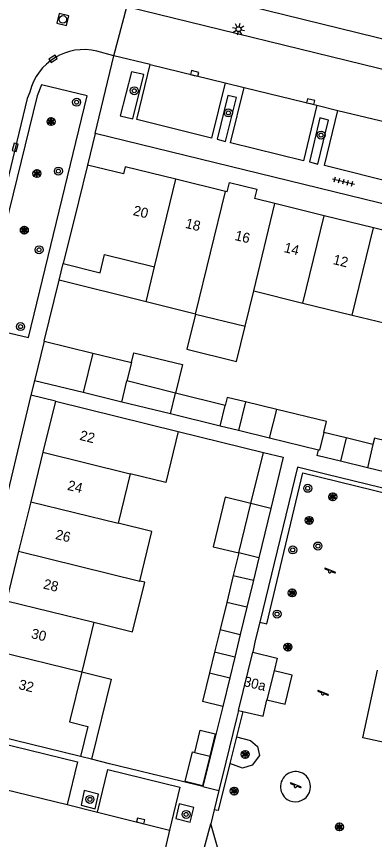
# Model space of a CAD drawing. Extents: x 128000 to 131008, y 398996 to 402500.
# Drawn here: x 128150.1 to 128186, y 399561.8 to 399644.1 of the extents above; entities that cross this region are included whole.
import ezdxf

# ---------------------------------------------------------------- set-up
doc = ezdxf.new("R2010")
doc.units = 0
for name, color, linetype in [('gg-afsc-hekwerk', 7, 'Continuous'), ('gg-afsc-muur', 7, 'Continuous'), ('gg-anno-huisnummerreeks BGT', 7, 'Continuous'), ('gg-bbg-bijgebouw', 7, 'Continuous'), ('gg-bbg-gedigitaliseerde bebouwing', 7, 'Continuous'), ('gg-bbg-gedigitaliseerde bijgebouw', 7, 'Continuous'), ('gg-bbg-hoofdgebouw', 7, 'Continuous'), ('gg-bbg-luifel en loopbrug', 7, 'Continuous'), ('gg-bbg-tussenscheiding', 7, 'Continuous'), ('gg-knt-verharding', 7, 'Continuous'), ('gg-knt-verharding nz', 7, 'Continuous'), ('gt-grn-groengrens', 7, 'Continuous'), ('gt-grn-weggrens', 7, 'Continuous'), ('gt-symb-boom', 7, 'Continuous'), ('gt-symb-kolk', 7, 'Continuous'), ('gt-symb-lichtmast', 7, 'Continuous'), ('gt-symb-rioolschacht', 7, 'Continuous'), ('gt-symb-solitaire heester', 7, 'Continuous'), ('gt-symb-speelvoorziening', 7, 'Continuous'), ('gt-symb-tegel verharding', 7, 'Continuous')]:
    doc.layers.add(name, color=color, linetype=linetype)

# ---------------------------------------------------------------- blocks, each defined once
blk = doc.blocks.new('gt0-BOOM')
at = {"layer": 'gt-symb-boom'}
for radius in [0.4, 0.2]:
    blk.add_circle((0, 0), radius, dxfattribs=at)
blk = doc.blocks.new('gt0-KOLK')
at = {"layer": 'gt-symb-kolk'}
blk.add_lwpolyline([(0, 0), (0.375, 0), (0.375, 0.4), (-0.375, 0.4), (-0.375, 0), (0, 0)], dxfattribs=at)
blk = doc.blocks.new('gt0-LMAST')
at = {"layer": 'gt-symb-lichtmast'}
for p, q in [((-0.182, 0.173), (-0.447, 0.438)), ((-0.005, 0.246), (-0.005, 0.621)), ((0.172, 0.173), (0.437, 0.438)), ((-0.255, -0.004), (-0.63, -0.004)), ((-0.182, -0.181), (-0.447, -0.446)), ((-0.005, -0.254), (-0.005, -0.629)), ((0.437, -0.446), (0.172, -0.181)), ((0.245, -0.004), (0.62, -0.004))]:
    blk.add_line(p, q, dxfattribs=at)
blk.add_circle((-0.005, -0.004), 0.25, dxfattribs=at)
blk = doc.blocks.new('gt0-TEG1')
at = {"layer": 'gt-symb-tegel verharding'}
for p, q in [((-1.125, 0), (1.125, 0)), ((-0.9, -0.25), (-0.9, 0.25)), ((-0.45, -0.25), (-0.45, 0.25)), ((0, -0.25), (0, 0.25)), ((0.45, -0.25), (0.45, 0.25)), ((0.9, -0.25), (0.9, 0.25))]:
    blk.add_line(p, q, dxfattribs=at)
blk = doc.blocks.new('gt0-SH')
at = {"layer": 'gt-symb-solitaire heester'}
blk.add_circle((0, 0), 0.4, dxfattribs=at)
for centre, start, end in [((-0.346, 0.2), 270, 30), ((-0.346, -0.2), 330, 90), ((0, 0.4), 210, 330), ((0.346, 0.2), 150, 270), ((0.346, -0.2), 90, 210), ((0, -0.4), 30, 150)]:
    blk.add_arc(centre, 0.4, start, end, dxfattribs=at)
blk = doc.blocks.new('gt0-RS')
at = {"layer": 'gt-symb-rioolschacht'}
blk.add_lwpolyline([(-0.5, -0.5), (0.5, -0.5), (0.5, 0.5), (-0.5, 0.5)], close=True, dxfattribs=at)
blk.add_circle((0, 0), 0.375, dxfattribs=at)
blk = doc.blocks.new('gt0-SV')
at = {"layer": 'gt-symb-speelvoorziening'}
for p, q in [((-0.477, 0.255), (-0.08, 0.096)), ((0.542, -0.076), (-0.449, 0.324)), ((0.125, 0.014), (0.515, -0.143))]:
    blk.add_line(p, q, dxfattribs=at)
for centre, radius, start, end in [((-0.466, 0.291), 0.0369, 63.6251, 252.66016), ((-0.002, -0.005), 0.128, 127.68665, 8.59861), ((0.531, -0.111), 0.0363, 243.50852, 72.54358)]:
    blk.add_arc(centre, radius, start, end, dxfattribs=at)

msp = doc.modelspace()

# ---------------------------------------------------------------- linework, layer by layer
at = {"layer": 'gg-afsc-hekwerk'}
for p, q in [((128203.553, 399592.827), (128181.209, 399598.288)), ((128171.084, 399569.505), (128170.393, 399566.665)), ((128170.393, 399566.665), (128169.92, 399564.721)), ((128169.92, 399564.721), (128169.58, 399563.327)), ((128170.982, 399558.462), (128169.58, 399563.327))]:
    msp.add_line(p, q, dxfattribs=at)
for points in [[(128181.209, 399598.288), (128178.265, 399599.008), (128174.493, 399583.51)], [(128174.493, 399583.51), (128174.043, 399581.663), (128173.796, 399580.492)], [(128172.372, 399574.674), (128172.145, 399573.865), (128171.084, 399569.505)]]:
    msp.add_lwpolyline(points, dxfattribs=at)
at = {"layer": 'gg-afsc-muur'}
for p, q in [((128152.897, 399611.62), (128154.389, 399617.73)), ((128166.312, 399602.605), (128174.854, 399600.506)), ((128170.783, 399575.069), (128168.797, 399567.055)), ((128159.426, 399569.345), (128157.621, 399569.786)), ((128166.623, 399567.586), (128159.426, 399569.345)), ((128168.797, 399567.055), (128166.623, 399567.586))]:
    msp.add_line(p, q, dxfattribs=at)
at = {"layer": 'gg-bbg-bijgebouw'}
for p, q in [((128152.897, 399611.62), (128151.932, 399607.671)), ((128156.798, 399606.485), (128151.932, 399607.671)), ((128165.548, 399604.353), (128160.667, 399605.542)), ((128170.52, 399603.141), (128165.548, 399604.353)), ((128175.477, 399601.933), (128172.373, 399602.689)), ((128180.377, 399600.739), (128175.477, 399601.933)), ((128185.268, 399598.962), (128182.569, 399599.625)), ((128190.194, 399597.752), (128185.268, 399598.962)), ((128175.605, 399594.896), (128174.401, 399589.946)), ((128173.854, 399587.697), (128173.197, 399584.995)), ((128173.197, 399584.995), (128172.539, 399582.291)), ((128171.485, 399577.954), (128170.783, 399575.069)), ((128170.783, 399575.069), (128168.76, 399575.57))]:
    msp.add_line(p, q, dxfattribs=at)
msp.add_lwpolyline([(128174.854, 399600.506), (128176.849, 399600.012), (128175.605, 399594.896)], dxfattribs=at)
at = {"layer": 'gg-bbg-gedigitaliseerde bebouwing'}
for p, q in [((128163.094, 399615.561), (128163.958, 399619.088)), ((128173.03, 399613.127), (128173.894, 399616.656)), ((128173.894, 399616.656), (128178.819, 399615.451)), ((128168.065, 399614.343), (128163.094, 399615.561)), ((128178.819, 399615.451), (128183.762, 399614.241)), ((128168.065, 399614.343), (128173.03, 399613.127)), ((128183.762, 399614.241), (128188.706, 399613.032)), ((128161.501, 399598.358), (128160.291, 399593.406)), ((128157.87, 399583.495), (128156.658, 399578.537))]:
    msp.add_line(p, q, dxfattribs=at)
for points in [[(128158.5, 399618.47), (128158.948, 399620.314), (128163.958, 399619.088)], [(128166.312, 399602.605), (128165.069, 399597.485), (128161.501, 399598.358)], [(128162.476, 399587.62), (128163.69, 399592.572), (128160.291, 399593.406)], [(128157.87, 399583.495), (128161.745, 399582.544), (128162.961, 399587.501), (128162.476, 399587.62)], [(128156.658, 399578.537), (128155.432, 399573.522), (128157.28, 399573.07)]]:
    msp.add_lwpolyline(points, dxfattribs=at)
at = {"layer": 'gg-bbg-gedigitaliseerde bijgebouw'}
for p, q in [((128152.897, 399611.62), (128157.76, 399610.432)), ((128157.76, 399610.432), (128156.798, 399606.485)), ((128160.667, 399605.542), (128161.178, 399607.65)), ((128166.05, 399606.413), (128161.178, 399607.65)), ((128171.021, 399605.201), (128166.05, 399606.413)), ((128170.52, 399603.141), (128171.021, 399605.201)), ((128173.07, 399605.548), (128172.373, 399602.689)), ((128176.184, 399604.789), (128173.07, 399605.548)), ((128183.134, 399601.944), (128182.569, 399599.625)), ((128185.834, 399601.287), (128183.134, 399601.944)), ((128173.596, 399595.381), (128174.854, 399600.506)), ((128172.384, 399590.436), (128173.596, 399595.381)), ((128174.401, 399589.946), (128172.384, 399590.436)), ((128171.836, 399588.188), (128171.178, 399585.487)), ((128171.836, 399588.188), (128173.854, 399587.697)), ((128171.178, 399585.487), (128170.519, 399582.783)), ((128170.519, 399582.783), (128172.539, 399582.291)), ((128169.462, 399578.448), (128168.76, 399575.57)), ((128169.462, 399578.448), (128171.485, 399577.954)), ((128167.98, 399570.459), (128169.491, 399570.09))]:
    msp.add_line(p, q, dxfattribs=at)
for points in [[(128180.899, 399602.488), (128181.165, 399603.577), (128176.184, 399604.789)], [(128180.899, 399602.488), (128180.468, 399600.717), (128180.377, 399600.739)], [(128190.924, 399600.71), (128185.986, 399601.912), (128185.834, 399601.287)], [(128167.02, 399567.562), (128167.742, 399570.518), (128167.98, 399570.459)], [(128169.491, 399570.09), (128168.769, 399567.135), (128167.02, 399567.562)]]:
    msp.add_lwpolyline(points, dxfattribs=at)
at = {"layer": 'gg-bbg-hoofdgebouw'}
for p, q in [((128157.233, 399629.251), (128156.339, 399625.59)), ((128166.084, 399627.835), (128161, 399629.08)), ((128171.046, 399626.62), (128166.084, 399627.835)), ((128171.22, 399626.577), (128171.046, 399626.62)), ((128176.007, 399625.405), (128173.96, 399625.906)), ((128156.339, 399625.59), (128154.797, 399619.402)), ((128180.959, 399624.192), (128176.007, 399625.405)), ((128185.892, 399622.984), (128180.959, 399624.192)), ((128190.863, 399621.767), (128185.892, 399622.984)), ((128154.797, 399619.402), (128158.5, 399618.47)), ((128154.011, 399605.626), (128152.756, 399600.51)), ((128154.011, 399605.626), (128166.312, 399602.605)), ((128152.756, 399600.51), (128151.541, 399595.557)), ((128151.541, 399595.557), (128150.326, 399590.604)), ((128150.326, 399590.604), (128149.111, 399585.651)), ((128172.372, 399574.674), (128173.796, 399580.492)), ((128173.796, 399580.492), (128176.225, 399579.898)), ((128176.225, 399579.898), (128175.917, 399578.635)), ((128175.917, 399578.635), (128175.213, 399575.742)), ((128172.372, 399574.674), (128172.785, 399574.579)), ((128157.28, 399573.07), (128156.54, 399570.05)), ((128156.54, 399570.05), (128147.86, 399572.18))]:
    msp.add_line(p, q, dxfattribs=at)
for points in [[(128161, 399629.08), (128160.826, 399628.371), (128157.233, 399629.251)], [(128171.22, 399626.577), (128171.451, 399627.52), (128174.193, 399626.858), (128173.96, 399625.906)], [(128172.785, 399574.579), (128174.816, 399574.11), (128175.213, 399575.742)]]:
    msp.add_lwpolyline(points, dxfattribs=at)
at = {"layer": 'gg-bbg-luifel en loopbrug'}
for p, q in [((128154.389, 399617.73), (128154.797, 399619.402)), ((128163.094, 399615.561), (128154.389, 399617.73)), ((128157.76, 399610.432), (128161.625, 399609.488)), ((128161.625, 399609.488), (128161.178, 399607.65)), ((128160.667, 399605.542), (128156.798, 399606.485)), ((128172.373, 399602.689), (128170.52, 399603.141)), ((128183.134, 399601.944), (128180.899, 399602.488)), ((128182.569, 399599.625), (128180.335, 399600.173)), ((128172.384, 399590.436), (128171.836, 399588.188)), ((128174.401, 399589.946), (128173.854, 399587.697)), ((128170.519, 399582.783), (128169.964, 399580.508)), ((128172.539, 399582.291), (128171.986, 399580.016)), ((128169.964, 399580.508), (128169.462, 399578.448)), ((128171.986, 399580.016), (128169.964, 399580.508)), ((128171.986, 399580.016), (128171.485, 399577.954)), ((128157.621, 399569.786), (128156.54, 399570.05))]:
    msp.add_line(p, q, dxfattribs=at)
for points in [[(128168.065, 399614.343), (128167.19, 399610.833), (128172.15, 399609.597), (128173.03, 399613.127)], [(128161.625, 399609.488), (128161.867, 399610.479), (128166.751, 399609.289), (128166.05, 399606.413)], [(128173.07, 399605.548), (128171.216, 399605.999), (128171.021, 399605.201)], [(128180.335, 399600.173), (128180.243, 399600.196), (128180.377, 399600.739)], [(128173.596, 399595.381), (128171.036, 399596.004), (128169.831, 399591.058), (128172.384, 399590.436)], [(128156.658, 399578.537), (128159.592, 399577.817), (128157.621, 399569.786)], [(128167.98, 399570.459), (128168.523, 399572.686), (128170.035, 399572.317), (128169.491, 399570.09)]]:
    msp.add_lwpolyline(points, dxfattribs=at)
at = {"layer": 'gg-bbg-tussenscheiding'}
for p, q in [((128163.958, 399619.088), (128166.084, 399627.835)), ((128168.065, 399614.343), (128171.046, 399626.62)), ((128173.894, 399616.656), (128176.007, 399625.405)), ((128178.819, 399615.451), (128180.959, 399624.192)), ((128183.762, 399614.241), (128185.892, 399622.984)), ((128165.548, 399604.353), (128166.05, 399606.413)), ((128175.477, 399601.933), (128176.184, 399604.789)), ((128185.834, 399601.287), (128185.268, 399598.962)), ((128152.756, 399600.51), (128161.501, 399598.358)), ((128151.541, 399595.557), (128160.291, 399593.406)), ((128175.605, 399594.896), (128173.596, 399595.381)), ((128150.326, 399590.604), (128162.476, 399587.62)), ((128149.111, 399585.651), (128157.87, 399583.495)), ((128173.197, 399584.995), (128171.178, 399585.487)), ((128147.894, 399580.69), (128156.658, 399578.537))]:
    msp.add_line(p, q, dxfattribs=at)
at = {"layer": 'gg-knt-verharding'}
for p, q in [((128258.441, 399624.279), (128163.514, 399647.59)), ((128210.514, 399632.989), (128161.155, 399645.107)), ((128159.88, 399640.19), (128158.177, 399640.66)), ((128163.512, 399639.307), (128159.88, 399640.19)), ((128171.031, 399637.477), (128169.656, 399631.962)), ((128171.031, 399637.477), (128172.921, 399637.017)), ((128180.221, 399635.24), (128182.311, 399634.732)), ((128158.01, 399632.42), (128157.233, 399629.251)), ((128211.42, 399619.34), (128158.01, 399632.42)), ((128146.517, 399613.151), (128151.313, 399611.999)), ((128151.569, 399606.229), (128145.543, 399581.398)), ((128154.011, 399605.626), (128151.569, 399606.229)), ((128155.179, 399565.254), (128158.226, 399564.496)), ((128165.456, 399562.689), (128164.033, 399556.8))]:
    msp.add_line(p, q, dxfattribs=at)
for points in [[(128169.656, 399631.962), (128162.164, 399633.801), (128163.512, 399639.307)], [(128162.861, 399638.305), (128161.64, 399638.589), (128160.512, 399634.174), (128161.781, 399633.883), (128162.861, 399638.305)], [(128151.313, 399611.999), (128157.205, 399636.191), (128152.619, 399637.278), (128152.191, 399636.184), (128146.517, 399613.151)], [(128151.442, 399636.561), (128151.197, 399635.907), (128147.03, 399618.83)], [(128180.221, 399635.24), (128178.883, 399629.693), (128171.551, 399631.494), (128172.921, 399637.017)], [(128172.161, 399636.011), (128171.288, 399636.224), (128170.206, 399631.836), (128171.068, 399631.601), (128172.161, 399636.011)], [(128189.64, 399632.949), (128188.279, 399627.384), (128180.981, 399629.222), (128182.311, 399634.732)], [(128181.374, 399633.759), (128180.523, 399633.977), (128179.463, 399629.575), (128180.32, 399629.354), (128181.374, 399633.759)], [(128175.213, 399575.742), (128177.021, 399575.302), (128177.725, 399578.195), (128175.917, 399578.635)], [(128191.633, 399570.474), (128184.823, 399571.935), (128186.297, 399578.705)], [(128145.63, 399568.138), (128146.517, 399571.9), (128156.22, 399569.517), (128155.179, 399565.254)], [(128158.226, 399564.496), (128159.273, 399568.752), (128166.498, 399567.003), (128165.456, 399562.689)], [(128156.581, 399565.2), (128158.008, 399564.84), (128158.347, 399566.293), (128156.912, 399566.664), (128156.581, 399565.2)], [(128166.071, 399563.873), (128167.513, 399563.506), (128167.872, 399564.95), (128166.416, 399565.312), (128166.071, 399563.873)], [(128170.982, 399558.462), (128168.43, 399559.01), (128169.58, 399563.327)]]:
    msp.add_lwpolyline(points, dxfattribs=at)
msp.add_arc((128156.868, 399635.228), 5.587, 76.44909, 166.20128, dxfattribs=at)
at = {"layer": 'gg-knt-verharding nz'}
for p, q in [((128163.512, 399639.307), (128171.031, 399637.477)), ((128172.921, 399637.017), (128180.221, 399635.24)), ((128182.311, 399634.732), (128189.64, 399632.949)), ((128158.226, 399564.496), (128165.456, 399562.689))]:
    msp.add_line(p, q, dxfattribs=at)
msp.add_lwpolyline([(128145.102, 399567.701), (128148.875, 399566.802), (128155.179, 399565.254)], dxfattribs=at)
at = {"layer": 'gt-grn-groengrens'}
for p, q in [((128172.785, 399574.579), (128172.147, 399572.018)), ((128172.147, 399572.018), (128171.484, 399569.36))]:
    msp.add_line(p, q, dxfattribs=at)
for points in [[(128174.493, 399583.51), (128175.194, 399583.34), (128178.789, 399598.441), (128203.453, 399592.417)], [(128172.147, 399572.018), (128173.552, 399571.65), (128174.251, 399571.064), (128174.475, 399570.153), (128173.727, 399569.19), (128172.751, 399568.899), (128171.484, 399569.36)], [(128171.484, 399569.36), (128170.311, 399564.652), (128169.92, 399564.721)]]:
    msp.add_lwpolyline(points, dxfattribs=at)
for centre, start, end in [((128178.085, 399567.036), 56.12149, 236.22618), ((128178.06, 399567.052), 237.35839, 54.98929)]:
    msp.add_arc(centre, 1.518, start, end, dxfattribs=at)
at = {"layer": 'gt-grn-weggrens'}
for p, q in [((128159.88, 399640.19), (128161.155, 399645.107)), ((128158.01, 399632.42), (128159.88, 399640.19)), ((128151.932, 399607.671), (128151.569, 399606.229)), ((128168.797, 399567.055), (128170.393, 399566.665))]:
    msp.add_line(p, q, dxfattribs=at)

# ---------------------------------------------------------------- block references
at = {"layer": 'gt-symb-boom'}
for p in [(128161.915, 399636.693), (128156.135, 399635.547), (128171.352, 399634.47), (128180.632, 399632.257), (128154.311, 399628.648), (128152.38, 399620.779), (128150.521, 399613.091), (128180.32, 399591.131), (128157.476, 399565.77), (128167.115, 399564.267)]:
    msp.add_blockref('gt0-BOOM', p, dxfattribs=at)
for p, rotation in [((128179.295, 399596.904), -13.716469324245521), ((128177.789, 399590.735), -13.716469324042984), ((128176.223, 399584.323), -13.71646932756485)]:
    msp.add_blockref('gt0-BOOM', p, dxfattribs=dict(at, rotation=rotation))
at = {"layer": 'gt-symb-kolk'}
for p, rotation in [((128153.673, 399640.053), -146.5005999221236), ((128167.925, 399638.228), -13.772145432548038), ((128179.54, 399635.405), -13.772145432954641), ((128149.788, 399631.07), -104.3002774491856), ((128162.498, 399563.429), -14.051900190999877)]:
    msp.add_blockref('gt0-KOLK', p, dxfattribs=dict(at, rotation=rotation))
at = {"layer": 'gt-symb-lichtmast', "rotation": -13.77214543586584}
msp.add_blockref('gt0-LMAST', (128172.376, 399642.861), dxfattribs=at)
at = {"layer": 'gt-symb-rioolschacht', "rotation": -103.82779503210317}
msp.add_blockref('gt0-RS', (128154.767, 399643.838), dxfattribs=at)
at = {"layer": 'gt-symb-solitaire heester'}
for p in [(128153.579, 399633.606), (128152.162, 399628.41), (128150.902, 399622.742), (128181.807, 399596.057), (128179.448, 399593.694), (128177.739, 399586.437), (128177.313, 399581.02), (128173.031, 399570.272), (128171.928, 399566.602), (128182.474, 399563.016)]:
    msp.add_blockref('gt0-SH', p, dxfattribs=at)
at = {"layer": 'gt-symb-speelvoorziening'}
for p in [(128181.501, 399588.578), (128180.799, 399576.352), (128178.063, 399567.096)]:
    msp.add_blockref('gt0-SV', p, dxfattribs=at)
at = {"layer": 'gt-symb-tegel verharding', "rotation": -13.82779503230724}
msp.add_blockref('gt0-TEG1', (128182.877, 399627.606), dxfattribs=at)

# ---------------------------------------------------------------- texts
at = {"layer": 'gg-anno-huisnummerreeks BGT'}
for s, rotation, p in [('20', 346.2, (128161.734, 399624.267)), ('18', 346.2, (128166.969, 399622.985)), ('16', 346.2, (128171.93, 399621.77)), ('14', 346.2, (128176.851, 399620.565)), ('12', 346.2, (128181.763, 399619.362)), ('22', 346.2, (128156.381, 399601.762)), ('24', 346.2, (128155.155, 399596.762)), ('26', 346.2, (128153.949, 399591.844)), ('28', 346.2, (128152.734, 399586.891)), ('30', 346.2, (128151.518, 399581.934)), ('30a', 346.3, (128172.805, 399577.135)), ('32', 346.2, (128150.266, 399576.832))]:
    msp.add_text(s, height=1, rotation=rotation, dxfattribs=at).set_placement(p)

doc.saveas('drawing.dxf')
